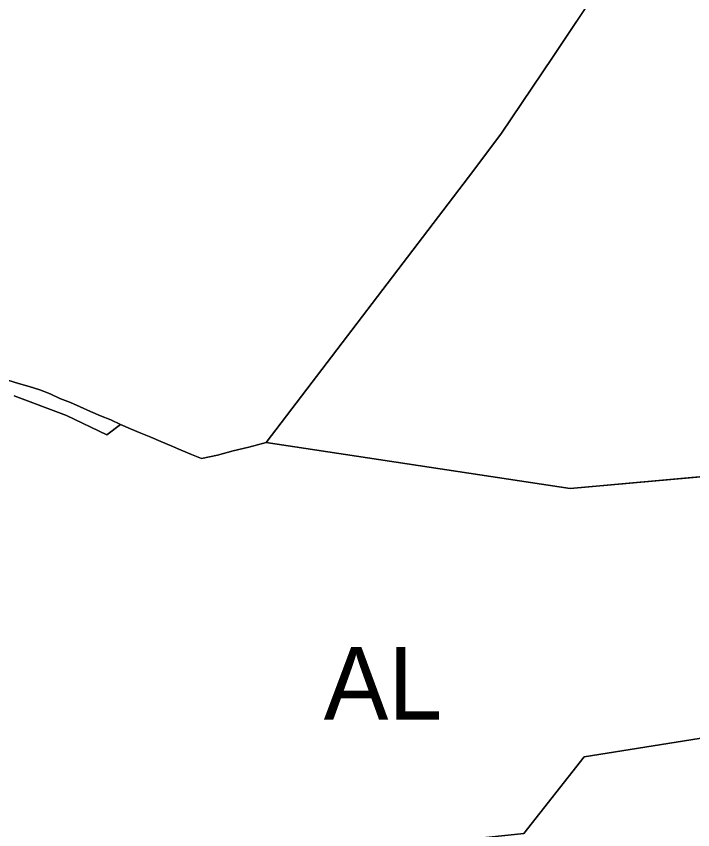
# Model space of a CAD drawing. Extents: x -555509 to -553005, y -1186756 to -1182560.
# Drawn here: x -554199.7 to -554068.9, y -1185603.5 to -1185446.2 of the extents above; entities that cross this region are included whole.
import ezdxf

# ---------------------------------------------------------------- set-up
doc = ezdxf.new("R2010")
doc.units = 0
for name, color, linetype in [('Level 26', 7, 'Continuous'), ('Level 59', 7, 'Continuous'), ('OBRYS_PLOCH', 7, 'Continuous'), ('stav_AL', 7, 'Continuous'), ('stav_ZK', 7, 'Continuous'), ('stav_ZZ', 7, 'Continuous')]:
    doc.layers.add(name, color=color, linetype=linetype)

msp = doc.modelspace()

# ---------------------------------------------------------------- linework, layer by layer
at = {"layer": 'Level 26'}
for p, q in [((-554199.27, -1185517.18), (-554201.33, -1185516.56)), ((-554197.18, -1185517.76), (-554199.27, -1185517.18)), ((-554195.12, -1185518.42), (-554197.18, -1185517.76)), ((-554200.12, -1185519.62), (-554190, -1185523.4)), ((-554193.13, -1185519.22), (-554195.12, -1185518.42)), ((-554191.24, -1185520.1), (-554193.13, -1185519.22)), ((-554189.22, -1185520.88), (-554191.24, -1185520.1)), ((-554187.31, -1185521.74), (-554189.22, -1185520.88)), ((-554185.34, -1185522.61), (-554187.31, -1185521.74)), ((-554183.4, -1185523.44), (-554185.34, -1185522.61)), ((-554190, -1185523.4), (-554182.15, -1185527.13)), ((-554181.43, -1185524.26), (-554183.4, -1185523.44)), ((-554179.54, -1185525.12), (-554181.43, -1185524.26)), ((-554182.15, -1185527.13), (-554179.54, -1185525.12))]:
    msp.add_line(p, q, dxfattribs=at)
at = {"layer": 'OBRYS_PLOCH'}
for p, q in [((-554086.65, -1185440.17), (-554095.82, -1185454)), ((-554112.25, -1185477.32), (-554151.37, -1185528.59)), ((-554199.27, -1185517.18), (-554201.33, -1185516.56)), ((-554197.18, -1185517.76), (-554199.27, -1185517.18)), ((-554195.12, -1185518.42), (-554197.18, -1185517.76)), ((-554200.12, -1185519.62), (-554190, -1185523.4)), ((-554190, -1185523.4), (-554182.15, -1185527.13)), ((-554181.43, -1185524.26), (-554183.4, -1185523.44)), ((-554179.54, -1185525.12), (-554181.43, -1185524.26)), ((-554182.15, -1185527.13), (-554179.54, -1185525.12)), ((-554092.59, -1185537.49), (-554151.37, -1185528.59)), ((-554151.37, -1185528.59), (-554092.59, -1185537.49)), ((-554092.59, -1185537.49), (-554035.44, -1185532.35))]:
    msp.add_line(p, q, dxfattribs=at)
for points in [[(-553973.36, -1185402.64), (-553974.35, -1185411.9), (-553991.45, -1185519.3), (-554035.44, -1185532.35), (-554092.59, -1185537.49)], [(-554179.54, -1185525.12), (-554177.58, -1185525.99), (-554175.6, -1185526.81), (-554173.67, -1185527.6), (-554171.7, -1185528.43), (-554169.73, -1185529.26), (-554167.81, -1185530.09), (-554165.79, -1185530.93), (-554163.85, -1185531.71), (-554160.8, -1185531.03), (-554157.75, -1185530.22), (-554154.73, -1185529.5), (-554151.37, -1185528.59), (-554112.25, -1185477.32), (-554105.95, -1185469.05), (-554095.82, -1185454), (-554086.65, -1185440.17)], [(-554095.82, -1185454), (-554105.95, -1185469.05), (-554112.25, -1185477.32)], [(-554201.33, -1185516.56), (-554199.27, -1185517.18), (-554197.18, -1185517.76), (-554195.12, -1185518.42), (-554193.13, -1185519.22), (-554191.24, -1185520.1), (-554189.22, -1185520.88), (-554187.31, -1185521.74), (-554185.34, -1185522.61), (-554183.4, -1185523.44), (-554181.43, -1185524.26), (-554179.54, -1185525.12)], [(-554179.54, -1185525.12), (-554182.15, -1185527.13), (-554190, -1185523.4), (-554200.12, -1185519.62)], [(-554189.22, -1185520.88), (-554191.24, -1185520.1), (-554193.13, -1185519.22), (-554195.12, -1185518.42)], [(-554183.4, -1185523.44), (-554185.34, -1185522.61), (-554187.31, -1185521.74), (-554189.22, -1185520.88)], [(-554151.37, -1185528.59), (-554154.73, -1185529.5), (-554157.75, -1185530.22), (-554160.8, -1185531.03), (-554163.85, -1185531.71), (-554165.79, -1185530.93), (-554167.81, -1185530.09), (-554169.73, -1185529.26), (-554171.7, -1185528.43), (-554173.67, -1185527.6), (-554175.6, -1185526.81), (-554177.58, -1185525.99), (-554179.54, -1185525.12)], [(-553963.43, -1185534.75), (-553971.86, -1185570.57), (-554019.93, -1185577.88), (-554049.8, -1185583.01), (-554089.83, -1185589.39), (-554101.5, -1185604.16), (-554154.04, -1185609.73), (-554179.93, -1185693.74)], [(-554179.93, -1185693.74), (-554154.04, -1185609.73), (-554101.5, -1185604.16), (-554089.83, -1185589.39), (-554049.8, -1185583.01), (-554019.93, -1185577.88), (-553971.86, -1185570.57), (-553963.43, -1185534.75)]]:
    msp.add_lwpolyline(points, dxfattribs=at)
at = {"layer": 'stav_AL'}
msp.add_line((-554092.59, -1185537.49), (-554151.37, -1185528.59), dxfattribs=at)
for points in [[(-553973.36, -1185402.64), (-553974.35, -1185411.9), (-553991.45, -1185519.3), (-554035.44, -1185532.35), (-554092.59, -1185537.49)], [(-554179.54, -1185525.12), (-554182.15, -1185527.13), (-554190, -1185523.4), (-554200.12, -1185519.62)], [(-554151.37, -1185528.59), (-554154.73, -1185529.5), (-554157.75, -1185530.22), (-554160.8, -1185531.03), (-554163.85, -1185531.71), (-554165.79, -1185530.93), (-554167.81, -1185530.09), (-554169.73, -1185529.26), (-554171.7, -1185528.43), (-554173.67, -1185527.6), (-554175.6, -1185526.81), (-554177.58, -1185525.99), (-554179.54, -1185525.12)], [(-554179.93, -1185693.74), (-554154.04, -1185609.73), (-554101.5, -1185604.16), (-554089.83, -1185589.39), (-554049.8, -1185583.01), (-554019.93, -1185577.88), (-553971.86, -1185570.57), (-553963.43, -1185534.75)]]:
    msp.add_lwpolyline(points, dxfattribs=at)
at = {"layer": 'stav_ZK'}
for p, q in [((-554086.65, -1185440.17), (-554095.82, -1185454)), ((-554095.82, -1185454), (-554105.95, -1185469.05)), ((-554105.95, -1185469.05), (-554112.25, -1185477.32)), ((-554112.25, -1185477.32), (-554151.37, -1185528.59)), ((-554151.37, -1185528.59), (-554092.59, -1185537.49)), ((-554092.59, -1185537.49), (-554035.44, -1185532.35))]:
    msp.add_line(p, q, dxfattribs=at)
msp.add_lwpolyline([(-553963.43, -1185534.75), (-553971.86, -1185570.57), (-554019.93, -1185577.88), (-554049.8, -1185583.01), (-554089.83, -1185589.39), (-554101.5, -1185604.16), (-554154.04, -1185609.73), (-554179.93, -1185693.74)], dxfattribs=at)
at = {"layer": 'stav_ZZ'}
for points in [[(-554179.54, -1185525.12), (-554177.58, -1185525.99), (-554175.6, -1185526.81), (-554173.67, -1185527.6), (-554171.7, -1185528.43), (-554169.73, -1185529.26), (-554167.81, -1185530.09), (-554165.79, -1185530.93), (-554163.85, -1185531.71), (-554160.8, -1185531.03), (-554157.75, -1185530.22), (-554154.73, -1185529.5), (-554151.37, -1185528.59), (-554112.25, -1185477.32), (-554105.95, -1185469.05), (-554095.82, -1185454), (-554086.65, -1185440.17)], [(-554201.33, -1185516.56), (-554199.27, -1185517.18), (-554197.18, -1185517.76), (-554195.12, -1185518.42), (-554193.13, -1185519.22), (-554191.24, -1185520.1), (-554189.22, -1185520.88), (-554187.31, -1185521.74), (-554185.34, -1185522.61), (-554183.4, -1185523.44), (-554181.43, -1185524.26), (-554179.54, -1185525.12)]]:
    msp.add_lwpolyline(points, dxfattribs=at)

# ---------------------------------------------------------------- texts
at = {"layer": 'Level 59'}
msp.add_text('AL', height=14, dxfattribs=at).set_placement((-554140.21, -1185582.15))

doc.saveas('drawing.dxf')
